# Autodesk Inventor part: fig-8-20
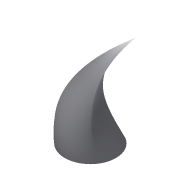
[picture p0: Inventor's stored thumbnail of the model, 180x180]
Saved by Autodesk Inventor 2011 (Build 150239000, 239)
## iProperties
Shininess: 77.0
Angle Display Precision: 2
Document Length Units: 11269
Document Angle Units: 11279
Document Time Units: 11290
Document Mass Units: 11283
Document Length Units Precision: 3
Document Angle Units Precision: 2
Created: 2001-12
Part Number: fig-8-20
Document SubType Name: Modeling
Designer: CADSoft
Density: 1 g/cm^3
Density: 0.0
Volumn: 0.0
Area: 0.0
PropertySet Name: Model Information
Control State: 0
Master: False
Checked Out: False
Author: CADSoft
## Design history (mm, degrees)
workplane "Work Plane3"
workplane "Work Plane4"
sketch "Sketch12"
  geometry: L1 (0, 10.598)-(9.178, -5.299); L2 (9.178, -5.299)-(-9.178, -5.299); L3 (-9.178, -5.299)-(0, 10.598); 1 further point
  constraints: 6 end point, 5 other
workplane "Work Plane5"
loft "Loft5" dims "d57" = 0, "d58" = 90 deg, "d59" = 0, "d60" = 90 deg, "d61" = 0, "d62" = 90 deg
body "Solid1"
sketch "Sketch1"
  geometry: C1 r 19.387 at (0, 0); 1 further point
  constraints: 1 centre point, 1 coincident, 1 other
sketch "Sketch2"
  geometry: 1 further point
